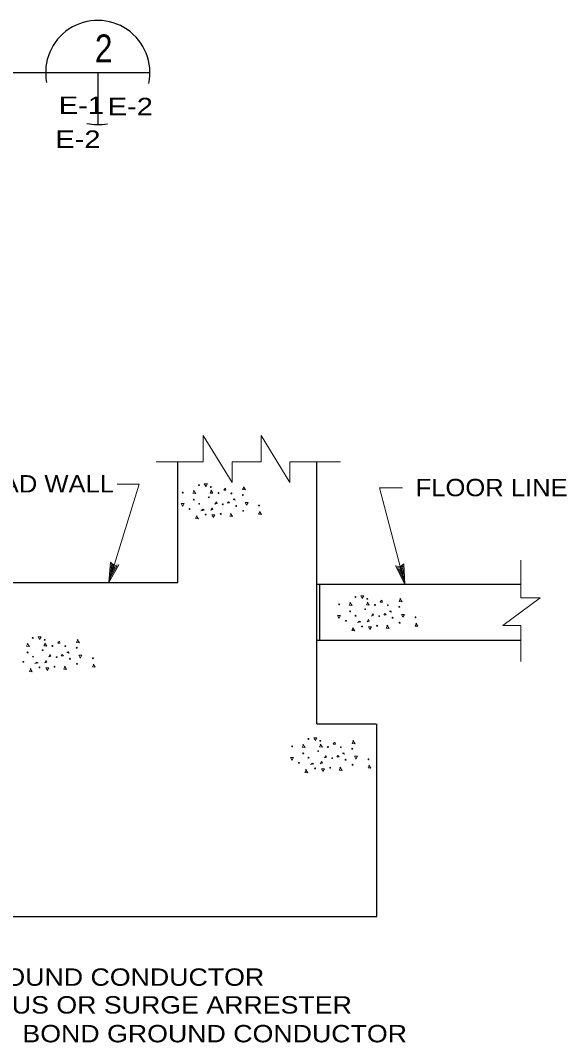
# Model space of a CAD drawing. Extents: x -39.6 to 16.1, y -17.6 to 34.
# Drawn here: x -5.01 to -1.08, y -2.68 to 4.68 of the extents above; entities that cross this region are included whole.
import ezdxf
from ezdxf.enums import TextEntityAlignment as Align

# ---------------------------------------------------------------- set-up
doc = ezdxf.new("R2010")
doc.units = 0
doc.header["$LTSCALE"] = 0.05
doc.layers.add('1', color=7, linetype='Continuous', lineweight=13)
doc.layers.add('2', color=7, linetype='Continuous', lineweight=13)

msp = doc.modelspace()

# ---------------------------------------------------------------- linework, layer by layer
at = {"layer": '1', "lineweight": 25}
for p, q in [((-6.78821, 4.30442), (-4.07921, 4.30442)), ((-4.45421, 4.30442), (-4.45421, 3.92942)), ((-3.87821, 0.63242), (-3.87821, 1.50142)), ((-2.87921, -0.38458), (-2.87921, 1.50142)), ((-10.28021, 0.63242), (-3.87821, 0.63242)), ((-2.87921, 0.62042), (-1.41221, 0.62042)), ((-2.85821, 0.21942), (-2.85821, 0.62042)), ((-2.87921, 0.21942), (-1.41221, 0.21942)), ((-2.87921, -0.38458), (-2.45421, -0.38458)), ((-2.44621, -1.77158), (-2.44621, -0.38458)), ((-6.38321, -1.77158), (-2.44621, -1.77158))]:
    msp.add_line(p, q, dxfattribs=at)
at = {"layer": '1'}
for p, q in [((-3.69521, 1.50142), (-3.69521, 1.69142)), ((-3.48821, 1.35442), (-3.69521, 1.69142)), ((-3.28021, 1.50142), (-3.28021, 1.69142)), ((-3.07321, 1.35442), (-3.28021, 1.69142)), ((-4.03321, 1.50142), (-3.69521, 1.50142)), ((-3.48821, 1.35442), (-3.48821, 1.50142)), ((-3.48821, 1.50142), (-3.28021, 1.50142)), ((-3.07321, 1.35442), (-3.07321, 1.50142)), ((-3.07321, 1.50142), (-2.70921, 1.50142)), ((-4.15721, 1.34142), (-4.37521, 0.63242)), ((-4.31421, 1.34142), (-4.15721, 1.34142)), ((-2.42721, 1.31542), (-2.26321, 1.31542)), ((-2.42721, 1.31542), (-2.24621, 0.62042)), ((-4.37521, 0.63242), (-4.36221, 0.77942)), ((-4.37521, 0.63242), (-4.30321, 0.76142)), ((-4.36421, 0.66742), (-4.35621, 0.76342)), ((-4.36421, 0.66742), (-4.31721, 0.75142)), ((-4.35621, 0.76342), (-4.33921, 0.74942)), ((-4.35421, 0.70242), (-4.35021, 0.74842)), ((-4.35421, 0.70242), (-4.33221, 0.74242)), ((-4.35021, 0.74842), (-4.34121, 0.74142)), ((-4.34121, 0.74142), (-4.33221, 0.74242)), ((-4.33921, 0.74942), (-4.31721, 0.75142)), ((-2.24621, 0.62042), (-2.31221, 0.75242)), ((-2.25521, 0.65642), (-2.29821, 0.74242)), ((-2.29821, 0.74242), (-2.27721, 0.73842)), ((-2.27721, 0.73842), (-2.26021, 0.75242)), ((-2.27521, 0.73042), (-2.26721, 0.73642)), ((-2.26421, 0.69142), (-2.26721, 0.73642)), ((-2.25521, 0.65642), (-2.26021, 0.75242)), ((-2.24621, 0.62042), (-2.25221, 0.76742)), ((-1.41221, 0.52342), (-1.41221, 0.79442)), ((-2.26421, 0.69142), (-2.28521, 0.73242)), ((-2.28521, 0.73242), (-2.27521, 0.73042)), ((-1.54021, 0.32442), (-1.27221, 0.52342)), ((-1.41221, 0.52342), (-1.27221, 0.52342)), ((-1.54021, 0.32442), (-1.41221, 0.32442)), ((-1.41221, 0.06442), (-1.41221, 0.32442))]:
    msp.add_line(p, q, dxfattribs=at)
for points in [[(-4.36221, 0.77942), (-4.33721, 0.75642), (-4.30321, 0.76142)], [(-2.31221, 0.75242), (-2.27921, 0.74642), (-2.25221, 0.76742)]]:
    msp.add_lwpolyline(points, dxfattribs=at)
at = {"layer": '1', "lineweight": 25}
for start, end in [(348.02387, 190.92017), (257.81974, 280.71312)]:
    msp.add_arc((-4.45421, 4.30442), 0.375, start, end, dxfattribs=at)
at = {"layer": '2'}
for p, q in [((-3.54721, 1.30142), (-3.53521, 1.31142)), ((-2.42221, 0.49642), (-2.41021, 0.50642)), ((-4.74221, 0.20142), (-4.73021, 0.21142)), ((-2.76021, -0.52558), (-2.74821, -0.51558))]:
    msp.add_line(p, q, dxfattribs=at)
for points in [[(-3.67821, 1.32642), (-3.68821, 1.34342), (-3.66621, 1.34342), (-3.67821, 1.32242)], [(-3.76121, 1.29542), (-3.77121, 1.27542), (-3.75021, 1.27342), (-3.76621, 1.29542)], [(-3.63621, 1.29742), (-3.64621, 1.27742), (-3.62621, 1.27542), (-3.64121, 1.29742)], [(-3.53521, 1.31242), (-3.53221, 1.29742), (-3.54721, 1.29742)], [(-3.40221, 1.32242), (-3.41221, 1.30242), (-3.39121, 1.30042), (-3.40721, 1.32242)], [(-3.84521, 1.18442), (-3.85521, 1.20142), (-3.83321, 1.20142), (-3.84521, 1.18042)], [(-3.52221, 1.20642), (-3.51521, 1.21442), (-3.50621, 1.20642), (-3.52021, 1.20442)], [(-3.48121, 1.23242), (-3.47121, 1.23542), (-3.46621, 1.22542), (-3.48121, 1.23042)], [(-3.38521, 1.19242), (-3.39521, 1.20942), (-3.37321, 1.20942), (-3.38521, 1.18942)], [(-3.74121, 1.11342), (-3.75121, 1.09342), (-3.73021, 1.09142), (-3.74621, 1.11342)], [(-3.70721, 1.15442), (-3.69721, 1.16042), (-3.68821, 1.15442), (-3.71221, 1.15042)], [(-3.62321, 1.10342), (-3.63321, 1.12042), (-3.61121, 1.12042), (-3.62321, 1.10042)], [(-3.49421, 1.13042), (-3.50421, 1.11042), (-3.48421, 1.10842), (-3.49921, 1.13042)], [(-3.28721, 1.14542), (-3.29721, 1.12542), (-3.27721, 1.12342), (-3.29221, 1.14542)], [(-2.55321, 0.52142), (-2.56321, 0.53842), (-2.54121, 0.53842), (-2.55321, 0.51742)], [(-2.27721, 0.51742), (-2.28721, 0.49742), (-2.26621, 0.49542), (-2.28221, 0.51742)], [(-2.63621, 0.49042), (-2.64621, 0.47042), (-2.62521, 0.46842), (-2.64121, 0.49042)], [(-2.51121, 0.49242), (-2.52121, 0.47242), (-2.50121, 0.47042), (-2.51621, 0.49242)], [(-2.41021, 0.50742), (-2.40721, 0.49242), (-2.42221, 0.49242)], [(-2.72021, 0.37942), (-2.73021, 0.39642), (-2.70821, 0.39642), (-2.72021, 0.37542)], [(-2.39721, 0.40142), (-2.39021, 0.40942), (-2.38121, 0.40142), (-2.39521, 0.39942)], [(-2.35621, 0.42742), (-2.34621, 0.43042), (-2.34121, 0.42042), (-2.35621, 0.42542)], [(-2.26021, 0.38742), (-2.27021, 0.40442), (-2.24821, 0.40442), (-2.26021, 0.38442)], [(-2.61621, 0.30842), (-2.62621, 0.28842), (-2.60521, 0.28642), (-2.62121, 0.30842)], [(-2.58221, 0.34942), (-2.57221, 0.35542), (-2.56321, 0.34942), (-2.58721, 0.34542)], [(-2.49821, 0.29842), (-2.50821, 0.31542), (-2.48621, 0.31542), (-2.49821, 0.29542)], [(-2.36921, 0.32542), (-2.37921, 0.30542), (-2.35921, 0.30342), (-2.37421, 0.32542)], [(-2.16221, 0.34042), (-2.17221, 0.32042), (-2.15221, 0.31842), (-2.16721, 0.34042)], [(-4.87321, 0.22642), (-4.88321, 0.24342), (-4.86121, 0.24342), (-4.87321, 0.22242)], [(-4.59721, 0.22242), (-4.60721, 0.20242), (-4.58621, 0.20042), (-4.60221, 0.22242)], [(-4.95621, 0.19542), (-4.96621, 0.17542), (-4.94521, 0.17342), (-4.96121, 0.19542)], [(-4.83121, 0.19742), (-4.84121, 0.17742), (-4.82121, 0.17542), (-4.83621, 0.19742)], [(-4.73021, 0.21242), (-4.72721, 0.19742), (-4.74221, 0.19742)], [(-4.71721, 0.10642), (-4.71021, 0.11442), (-4.70121, 0.10642), (-4.71521, 0.10442)], [(-4.67621, 0.13242), (-4.66621, 0.13542), (-4.66121, 0.12542), (-4.67621, 0.13042)], [(-4.58021, 0.09242), (-4.59021, 0.10942), (-4.56821, 0.10942), (-4.58021, 0.08942)], [(-4.93621, 0.01342), (-4.94621, -0.00658), (-4.92521, -0.00858), (-4.94121, 0.01342)], [(-4.90221, 0.05442), (-4.89221, 0.06042), (-4.88321, 0.05442), (-4.90721, 0.05042)], [(-4.81821, 0.00342), (-4.82821, 0.02042), (-4.80621, 0.02042), (-4.81821, 0.00042)], [(-4.68921, 0.03042), (-4.69921, 0.01042), (-4.67921, 0.00842), (-4.69421, 0.03042)], [(-4.48221, 0.04542), (-4.49221, 0.02542), (-4.47221, 0.02342), (-4.48721, 0.04542)], [(-2.89121, -0.50058), (-2.90121, -0.48358), (-2.87921, -0.48358), (-2.89121, -0.50458)], [(-2.74821, -0.51458), (-2.74521, -0.52958), (-2.76021, -0.52958)], [(-2.61521, -0.50458), (-2.62521, -0.52458), (-2.60421, -0.52658), (-2.62021, -0.50458)], [(-2.97421, -0.53158), (-2.98421, -0.55158), (-2.96321, -0.55358), (-2.97921, -0.53158)], [(-2.84921, -0.52958), (-2.85921, -0.54958), (-2.83921, -0.55158), (-2.85421, -0.52958)], [(-3.05821, -0.64258), (-3.06821, -0.62558), (-3.04621, -0.62558), (-3.05821, -0.64658)], [(-2.73521, -0.62058), (-2.72821, -0.61258), (-2.71921, -0.62058), (-2.73321, -0.62258)], [(-2.69421, -0.59458), (-2.68421, -0.59158), (-2.67921, -0.60158), (-2.69421, -0.59658)], [(-2.59821, -0.63458), (-2.60821, -0.61758), (-2.58621, -0.61758), (-2.59821, -0.63758)], [(-2.95421, -0.71358), (-2.96421, -0.73358), (-2.94321, -0.73558), (-2.95921, -0.71358)], [(-2.92021, -0.67258), (-2.91021, -0.66658), (-2.90121, -0.67258), (-2.92521, -0.67658)], [(-2.83621, -0.72358), (-2.84621, -0.70658), (-2.82421, -0.70658), (-2.83621, -0.72658)], [(-2.70721, -0.69658), (-2.71721, -0.71658), (-2.69721, -0.71858), (-2.71221, -0.69658)], [(-2.50021, -0.68158), (-2.51021, -0.70158), (-2.49021, -0.70358), (-2.50521, -0.68158)]]:
    msp.add_lwpolyline(points, dxfattribs=at)
for points in [[(-3.61121, 1.19742), (-3.60121, 1.21442), (-3.59621, 1.20242)], [(-3.64121, 1.15442), (-3.63121, 1.17142), (-3.62621, 1.15942)], [(-2.48621, 0.39242), (-2.47621, 0.40942), (-2.47121, 0.39742)], [(-2.51621, 0.34942), (-2.50621, 0.36642), (-2.50121, 0.35442)], [(-4.80621, 0.09742), (-4.79621, 0.11442), (-4.79121, 0.10242)], [(-4.83621, 0.05442), (-4.82621, 0.07142), (-4.82121, 0.05942)], [(-2.85421, -0.67258), (-2.84421, -0.65558), (-2.83921, -0.66758)], [(-2.82421, -0.62958), (-2.81421, -0.61258), (-2.80921, -0.62458)]]:
    msp.add_lwpolyline(points, close=True, dxfattribs=at)
for centre in [(-3.72671, 1.33417), (-3.84321, 1.28067), (-3.64121, 1.32067), (-3.58571, 1.27717), (-3.49321, 1.27517), (-3.41071, 1.26367), (-3.76371, 1.23017), (-3.72521, 1.19967), (-3.65621, 1.24667), (-3.55521, 1.19617), (-3.45921, 1.18467), (-3.29421, 1.18817), (-3.79421, 1.16267), (-3.67821, 1.12217), (-3.57021, 1.12717), (-3.40871, 1.14917), (-2.60171, 0.52917), (-2.51621, 0.51567), (-2.71821, 0.47567), (-2.53121, 0.44167), (-2.46071, 0.47217), (-2.36821, 0.47017), (-2.28571, 0.45867), (-2.63871, 0.42517), (-2.60021, 0.39467), (-2.43021, 0.39117), (-2.33421, 0.37967), (-2.16921, 0.38317), (-2.66921, 0.35767), (-2.55321, 0.31717), (-2.44521, 0.32217), (-2.28371, 0.34417), (-4.92171, 0.23417), (-4.83621, 0.22067), (-4.85121, 0.14667), (-4.78071, 0.17717), (-4.68821, 0.17517), (-4.60571, 0.16367), (-4.95871, 0.13017), (-4.92021, 0.09967), (-4.75021, 0.09617), (-4.65421, 0.08467), (-4.48921, 0.08817), (-4.98921, 0.06267), (-4.87321, 0.02217), (-4.76521, 0.02717), (-4.60371, 0.04917), (-2.93971, -0.49283), (-2.85421, -0.50633), (-3.05621, -0.54633), (-2.86921, -0.58033), (-2.79871, -0.54983), (-2.70621, -0.55183), (-2.62371, -0.56333), (-3.00721, -0.66433), (-2.97671, -0.59683), (-2.93821, -0.62733), (-2.76821, -0.63083), (-2.67221, -0.64233), (-2.50721, -0.63883), (-2.89121, -0.70483), (-2.78321, -0.69983), (-2.62171, -0.67783)]:
    msp.add_circle(centre, 0.00325, dxfattribs=at)

# ---------------------------------------------------------------- texts
at = {"layer": '1'}
for s, height, width, p in [('2', 0.2, 0.85, (-4.41171, 4.37842)), ('E-1', 0.125, 1.25, (-4.57221, 4.00642)), ('E-2', 0.125, 1.25, (-4.22021, 3.99742)), ('E-2', 0.125, 1.25, (-4.59721, 3.76242))]:
    msp.add_text(s, height=height, dxfattribs=dict(at, width=width)).set_placement(p, align=Align.CENTER)
for s, width, p in [('HEAD WALL', 1.1, (-5.40021, 1.28142)), ('FLOOR LINE', 1.1, (-2.16821, 1.25442)), ('#8 A.W.G. BARE COPPER GROUND CONDUCTOR', 1.15, (-7.7962, -2.26928)), ('TO PANELBOARD GROUND BUS OR SURGE ARRESTER', 1.15, (-7.7962, -2.46928)), ('WHERE INDICATED ON PLAN. BOND GROUND CONDUCTOR', 1.15, (-7.8052, -2.67628))]:
    msp.add_text(s, height=0.125, dxfattribs=dict(at, width=width)).set_placement(p)

doc.saveas('drawing.dxf')
